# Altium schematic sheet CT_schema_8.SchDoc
size 251 x 159 mm
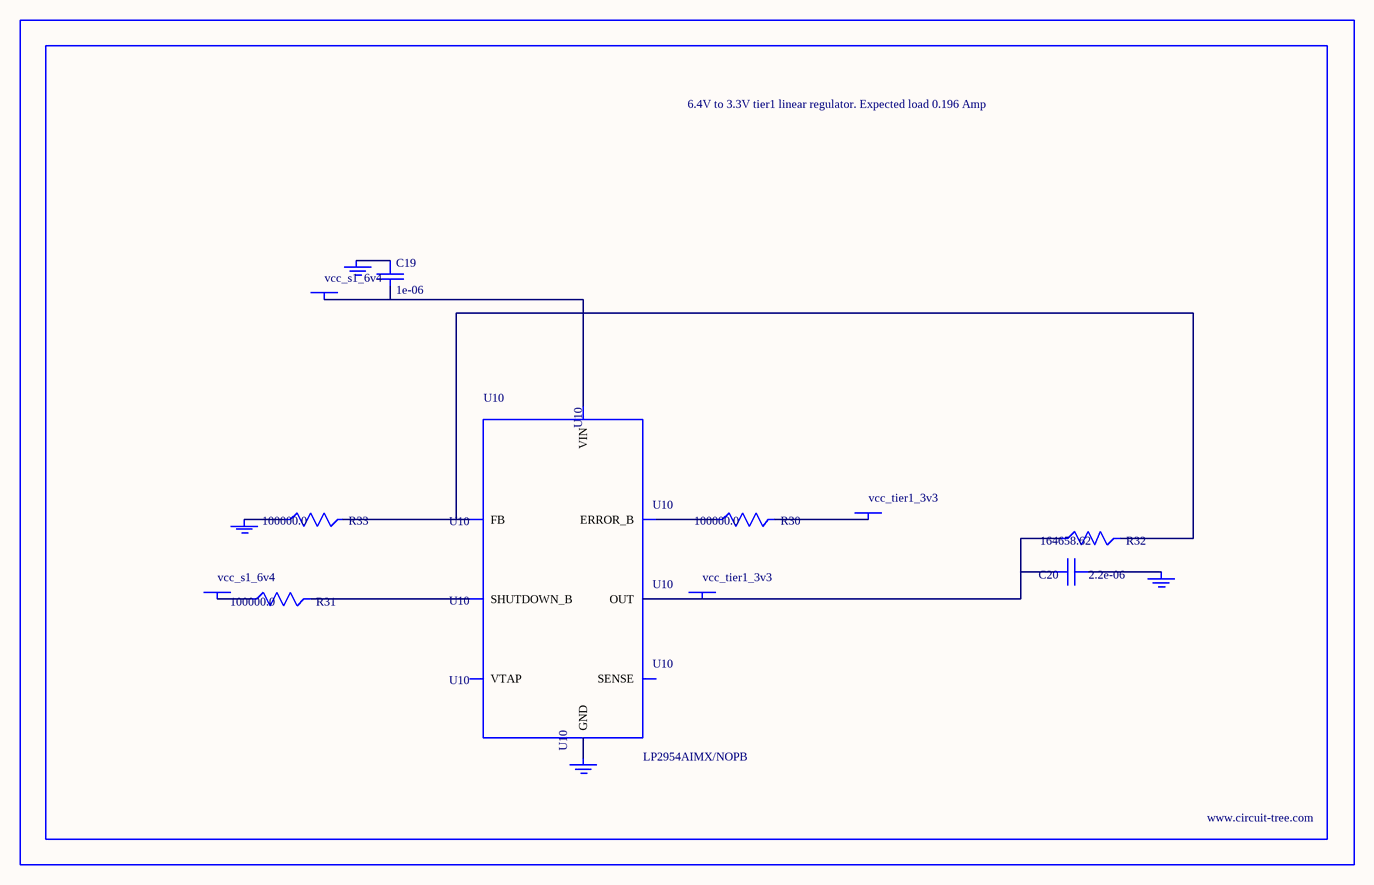
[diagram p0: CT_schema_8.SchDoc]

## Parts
BORDER7  (no value)
C19  1e-06  [EXV-9B]
C20  2.2e-06  [EXV-9B]
GND_INSTANCE_7_0  (no value)
GND_INSTANCE_7_1  (no value)
GND_INSTANCE_7_2  (no value)
GND_INSTANCE_7_3  (no value)
POWER_INSTANCE_7_0  vcc_s1_6v4
POWER_INSTANCE_7_1  vcc_tier1_3v3
POWER_INSTANCE_7_2  vcc_s1_6v4
POWER_INSTANCE_7_3  vcc_tier1_3v3
R30  100000.0  [R0603]
R31  100000.0  [R0603]
R32  164658.62  [R0603]
R33  100000.0  [R0603]
U10  LP2954AIMX/NOPB  [LP2954]

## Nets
NetC19_1: C19.1 GND_INSTANCE_7_2.0(GND)
NetC19_2: C19.2 POWER_INSTANCE_7_2.0(PWR) U10.8(VIN)
NetC20_1: C20.1 GND_INSTANCE_7_0.0(GND)
NetC20_2: C20.2 POWER_INSTANCE_7_3.0(PWR) R32.1 U10.1(OUT)
NetGND_INSTANCE_7_1_0: GND_INSTANCE_7_1.0(GND) R33.1
NetGND_INSTANCE_7_3_0: GND_INSTANCE_7_3.0(GND) U10.4(GND)
NetPOWER_INSTANCE_7_0_0: POWER_INSTANCE_7_0.0(PWR) R31.1
NetPOWER_INSTANCE_7_1_0: POWER_INSTANCE_7_1.0(PWR) R30.2
NetR30_1: R30.1 U10.5(ERROR_B)
NetR31_2: R31.2 U10.3(SHUTDOWN_B)
NetR32_2: R32.2 R33.2 U10.7(FB)

Not connected (* = marked no-connect by the designer): U10 2(SENSE) 6(VTAP)

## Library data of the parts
BORDER7 = BORDER_PAGE7
C19 = EDK105M050A9BAA
C20 = EDK225M050A9BAA
GND_INSTANCE_7_0-GND_INSTANCE_7_3 = GND
POWER_INSTANCE_7_0-POWER_INSTANCE_7_3 = PWR
R30 R31 R33 = RC0603JR-07100KL
R32 = R32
